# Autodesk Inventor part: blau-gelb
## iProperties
Created: 2004-10
Part Number: blau-gelb
Document SubType Name: Modeling
Designer: sahrens
Manufacturer: Standard
Standards Organization: Custom
Author: sahrens
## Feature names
1. Extrusion1
2. Rundung2 [Fillet]
